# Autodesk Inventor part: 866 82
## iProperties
Created: 2005-11
Part Number: 866 82
Material: 1.4301 X5CrNi10-10 A2
Description: Flansch KF 16 (lang)
Document SubType Name: Modellieren
Designer: Mittelmeyer
Manufacturer: Standard
Standards Organization: Custom
Author: Mittelmeyer
Comments: LEYBOLD
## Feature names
1. Extrusion2
2. Drehung1 [Revolution]
3. Bohrung1 [Hole]
